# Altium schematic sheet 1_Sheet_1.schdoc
size 497 x 241 mm; Name: NO_A4; Symbol: NO_A4; Device: NO_A4; @Project Name: esp32-hub75-driver-schem_2022-11-10_17-33-28; REV: 1.0; Date: 2019-10-07; Sheet: 1/1; Draw By: rorosaurus; Company: Your Company; Convert to PCB: yes; Add into BOM: yes
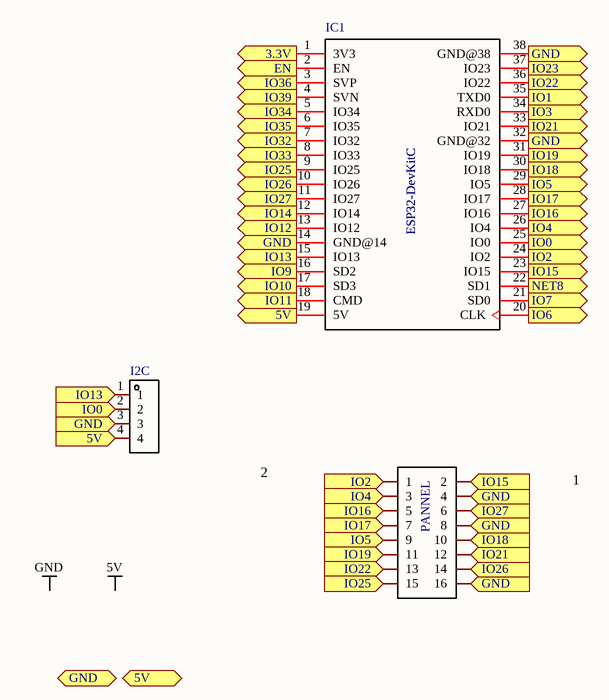
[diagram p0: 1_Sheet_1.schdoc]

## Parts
I2C  HDR-F_2.54_1x4P  [HDR-TH_4P-P2.54-V-F]  (value not drawn)
IC1  ESP32-DevKitC
PANNEL  HDR-F-2.54_2x8  [HDR-TH_16P-P2.54-V-F-R2-C8-S2.54-1]  (value not drawn)

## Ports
3.3V (out), 5V (bidir), 5V (in), 5V (out), EN (out), GND (bidir), GND (in), GND (out), IO0 (in), IO0 (out), IO1 (out), IO2 (in), IO2 (out), IO3 (out), IO4 (in), IO4 (out), IO5 (in), IO5 (out), IO6 (out), IO7 (out), IO9 (out), IO10 (out), IO11 (out), IO12 (out), IO13 (in), IO13 (out), IO14 (out), IO15 (in), IO15 (out), IO16 (in), IO16 (out), IO17 (in), IO17 (out), IO18 (in), IO18 (out), IO19 (in), IO19 (out), IO21 (in), IO21 (out), IO22 (in), IO22 (out), IO23 (out), IO25 (in), IO25 (out), IO26 (in), IO26 (out), IO27 (in), IO27 (out), IO32 (out), IO33 (out), IO34 (out), IO35 (out), IO36 (out), IO39 (out), NET8 (out)

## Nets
3.3V: IC1.1(3V3) ; port 3.3V
5V: I2C.4 IC1.19(5V) ; port 5V
EN: IC1.2(EN) ; port EN
GND: I2C.3 IC1.14(GND@14) IC1.32(GND@32) IC1.38(GND@38) PANNEL.4 PANNEL.8 PANNEL.16 ; port GND
IO0: I2C.2 IC1.25(IO0) ; port IO0
IO1: IC1.35(TXD0) ; port IO1
IO2: IC1.24(IO2) PANNEL.1 ; port IO2
IO3: IC1.34(RXD0) ; port IO3
IO4: IC1.26(IO4) PANNEL.3 ; port IO4
IO5: IC1.29(IO5) PANNEL.9 ; port IO5
IO6: IC1.20(CLK) ; port IO6
IO7: IC1.21(SD0) ; port IO7
IO9: IC1.16(SD2) ; port IO9
IO10: IC1.17(SD3) ; port IO10
IO11: IC1.18(CMD) ; port IO11
IO12: IC1.13(IO12) ; port IO12
IO13: I2C.1 IC1.15(IO13) ; port IO13
IO14: IC1.12(IO14) ; port IO14
IO15: IC1.23(IO15) PANNEL.2 ; port IO15
IO16: IC1.27(IO16) PANNEL.5 ; port IO16
IO17: IC1.28(IO17) PANNEL.7 ; port IO17
IO18: IC1.30(IO18) PANNEL.10 ; port IO18
IO19: IC1.31(IO19) PANNEL.11 ; port IO19
IO21: IC1.33(IO21) PANNEL.12 ; port IO21
IO22: IC1.36(IO22) PANNEL.13 ; port IO22
IO23: IC1.37(IO23) ; port IO23
IO25: IC1.9(IO25) PANNEL.15 ; port IO25
IO26: IC1.10(IO26) PANNEL.14 ; port IO26
IO27: IC1.11(IO27) PANNEL.6 ; port IO27
IO32: IC1.7(IO32) ; port IO32
IO33: IC1.8(IO33) ; port IO33
IO34: IC1.5(IO34) ; port IO34
IO35: IC1.6(IO35) ; port IO35
IO36: IC1.3(SVP) ; port IO36
IO39: IC1.4(SVN) ; port IO39
NET8: IC1.22(SD1) ; port NET8

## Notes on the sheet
- 2
- 1

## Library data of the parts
I2C = HDR-F_2.54_1x4P: Symbol: 2.54-1*4P母; Convert to PCB: yes
IC1 = ESP32-DEVKITC-32U_ESP32-DEVKITC-32U_: Add into BOM: yes
PANNEL = HDR-F-2.54_2x8: Add into BOM: yes; Value: f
